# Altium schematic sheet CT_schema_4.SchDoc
size 278 x 262 mm
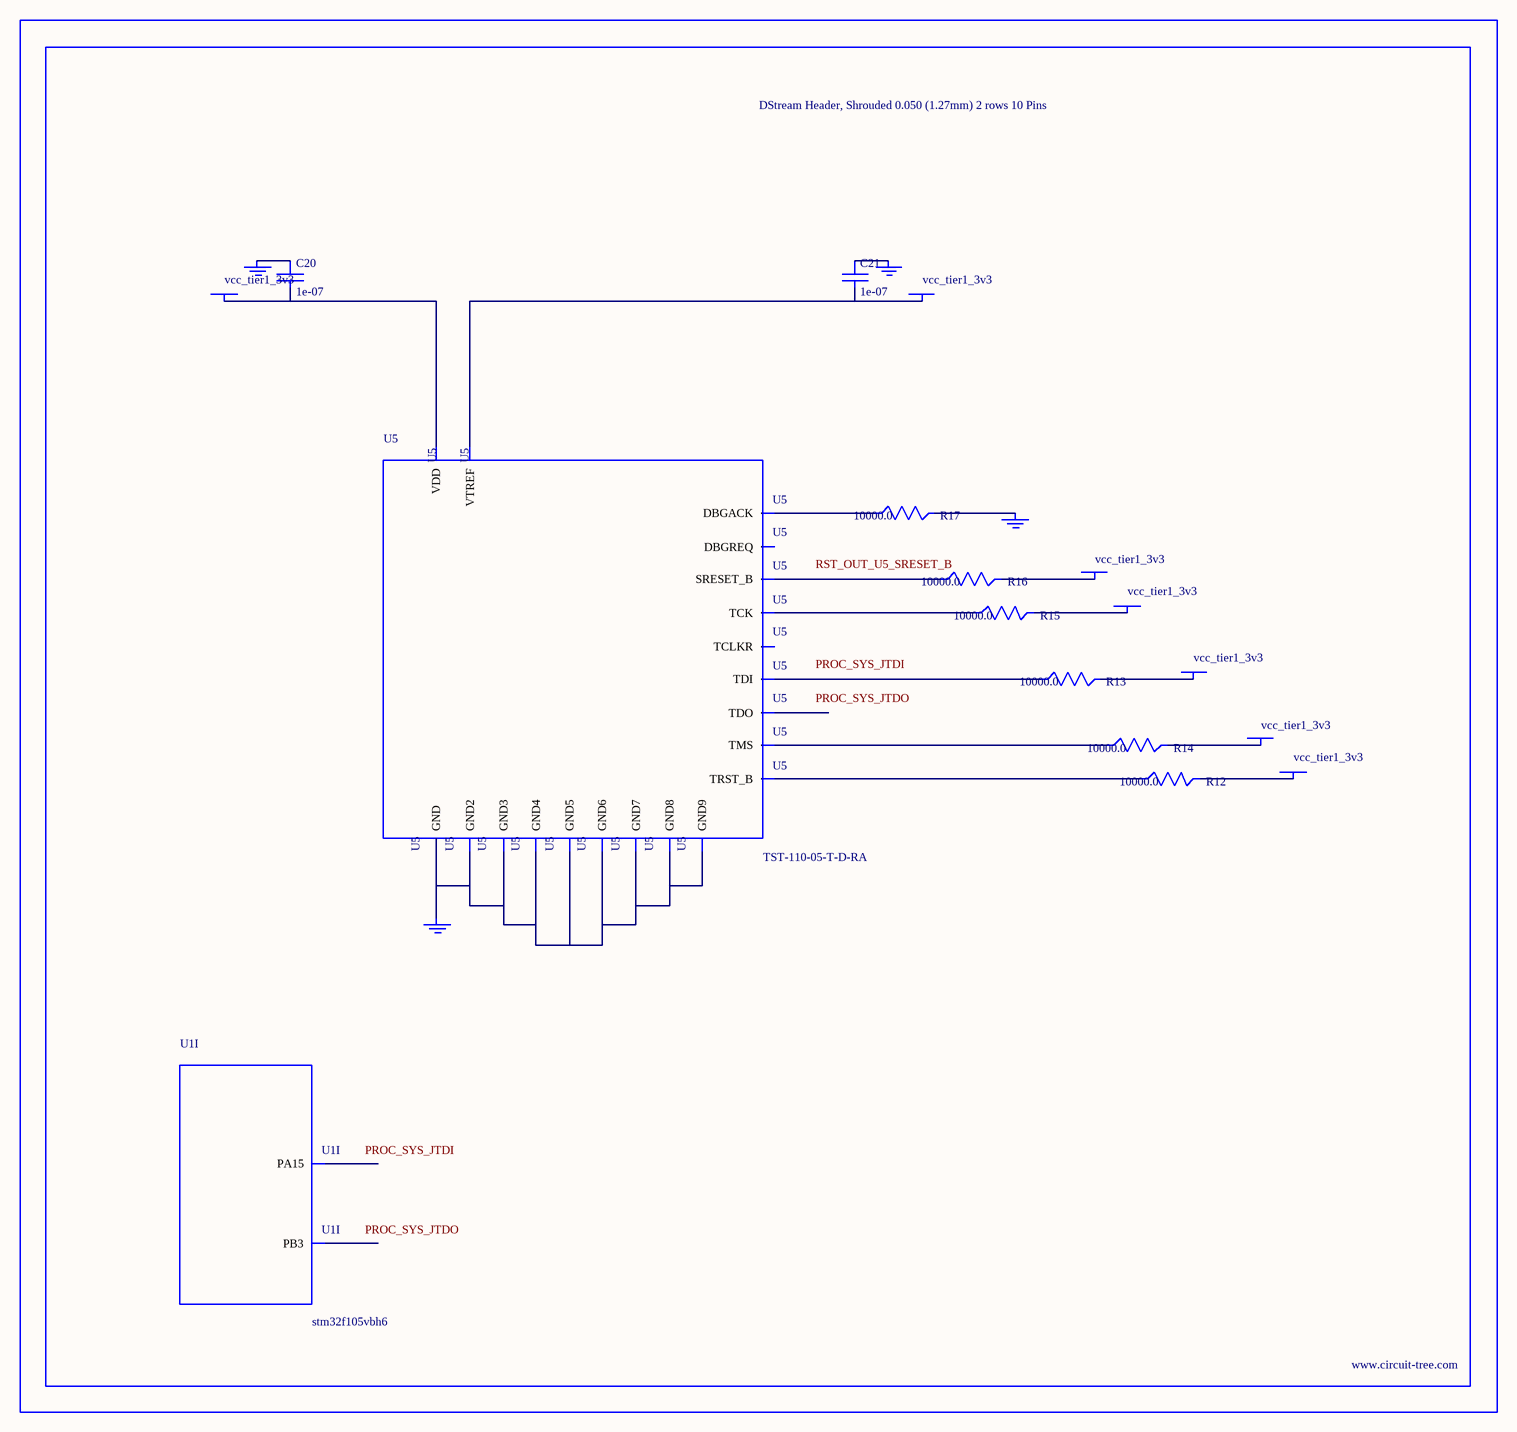
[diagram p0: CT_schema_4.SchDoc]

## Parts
BORDER3  (no value)
C20  1e-07  [C0402]
C21  1e-07  [C0402]
GND_INSTANCE_3_0  (no value)
GND_INSTANCE_3_1  (no value)
GND_INSTANCE_3_2  (no value)
GND_INSTANCE_3_3  (no value)
POWER_INSTANCE_3_0  vcc_tier1_3v3
POWER_INSTANCE_3_1  vcc_tier1_3v3
POWER_INSTANCE_3_2  vcc_tier1_3v3
POWER_INSTANCE_3_3  vcc_tier1_3v3
POWER_INSTANCE_3_4  vcc_tier1_3v3
POWER_INSTANCE_3_5  vcc_tier1_3v3
POWER_INSTANCE_3_6  vcc_tier1_3v3
R12  10000.0  [R0603]
R13  10000.0  [R0603]
R14  10000.0  [R0603]
R15  10000.0  [R0603]
R16  10000.0  [R0603]
R17  10000.0  [R0603]
U1  stm32f105vbh6  [LFBGA100]  (part I of 11)
U5  TST-110-05-T-D-RA  [TST-110-05-T-D-RA]

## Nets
NetC20_1: C20.1 GND_INSTANCE_3_1.0(GND)
NetC20_2: C20.2 POWER_INSTANCE_3_1.0(PWR) U5.2(VDD)
NetC21_1: C21.1 GND_INSTANCE_3_0.0(GND)
NetC21_2: C21.2 POWER_INSTANCE_3_0.0(PWR) U5.1(VTREF)
NetGND_INSTANCE_3_2_0: GND_INSTANCE_3_2.0(GND) R17.2
NetGND_INSTANCE_3_3_0: GND_INSTANCE_3_3.0(GND) U5.4(GND) U5.6(GND2) U5.8(GND3) U5.10(GND4) U5.12(GND5) U5.14(GND6) U5.16(GND7) U5.18(GND8) U5.20(GND9)
NetPOWER_INSTANCE_3_2_0: POWER_INSTANCE_3_2.0(PWR) R12.2
NetPOWER_INSTANCE_3_3_0: POWER_INSTANCE_3_3.0(PWR) R13.2
NetPOWER_INSTANCE_3_4_0: POWER_INSTANCE_3_4.0(PWR) R14.2
NetPOWER_INSTANCE_3_5_0: POWER_INSTANCE_3_5.0(PWR) R15.2
NetPOWER_INSTANCE_3_6_0: POWER_INSTANCE_3_6.0(PWR) R16.2
NetR12_1: R12.1 U5.3(TRST_B)
NetR13_1: R13.1 U5.5(TDI)
NetR14_1: R14.1 U5.7(TMS)
NetR15_1: R15.1 U5.9(TCK)
NetR16_1: R16.1 U5.15(SRESET_B)
NetR17_1: R17.1 U5.19(DBGACK)

Not connected (* = marked no-connect by the designer): U1 A7(PB3) A8(PA15); U5 11(TCLKR) 13(TDO) 17(DBGREQ)

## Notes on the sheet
- Labels drawn without touching a wire or pin: PROC_SYS_JTDI, PROC_SYS_JTDO, RST_OUT_U5_SRESET_B

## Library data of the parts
BORDER3 = BORDER_PAGE3
C20 C21 = C0402C104K3RACTU
GND_INSTANCE_3_0-GND_INSTANCE_3_3 = GND
POWER_INSTANCE_3_0-POWER_INSTANCE_3_6 = PWR
R12-R17 = RC0603JR-0710KL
